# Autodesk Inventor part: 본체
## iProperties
Company: 한국ATC센터
Created: 2015-04
Part Number: 본체
Document SubType Name: Modeling
Designer: KYOUNG IL JANG
Density: 2.71 g/cm^3
Material: 알루미늄-6061
Author: KYOUNG IL JANG
